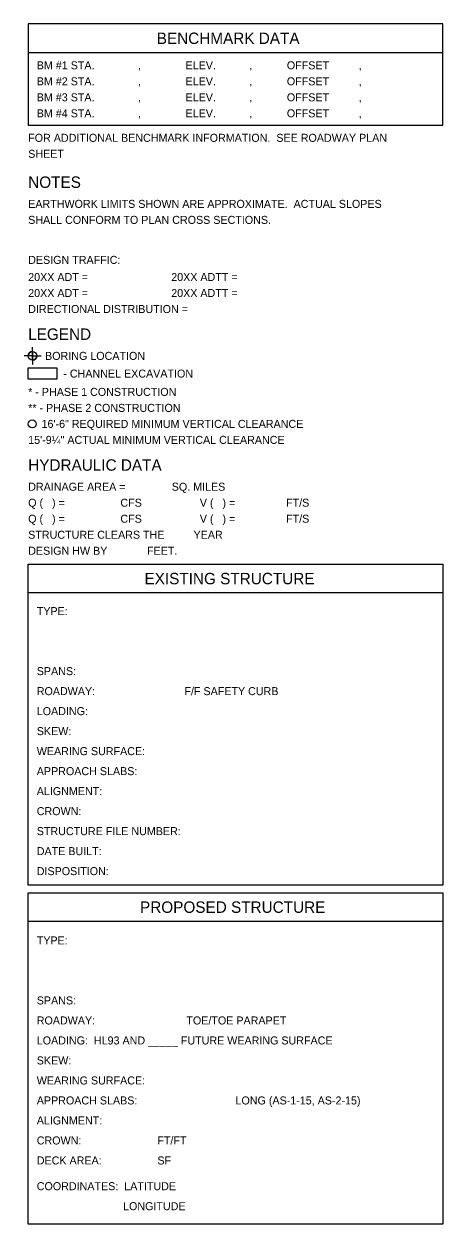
# Model space of a CAD drawing. Extents: x 0 to 112, y 0 to 22.
# Drawn here: x 60.68 to 68, y 0.5 to 21.5 of the extents above; entities that cross this region are included whole.
import ezdxf

# ---------------------------------------------------------------- set-up
doc = ezdxf.new("R2010")
doc.units = 0
doc.layers.add('GT_Project_Soil_Boring', color=7, linetype='Continuous')
doc.layers.add('SH_Data', color=7, linetype='Continuous')

msp = doc.modelspace()

# ---------------------------------------------------------------- linework, layer by layer
at = {"layer": 'GT_Project_Soil_Boring'}
for p, q in [((60.827, 15.693), (60.827, 15.843)), ((60.827, 15.768), (60.827, 15.693)), ((60.827, 15.693), (60.677, 15.693)), ((60.827, 15.693), (60.752, 15.693)), ((60.827, 15.693), (60.827, 15.543)), ((60.827, 15.693), (60.977, 15.693)), ((60.827, 15.618), (60.827, 15.693)), ((60.827, 15.693), (60.902, 15.693))]:
    msp.add_line(p, q, dxfattribs=at)
msp.add_circle((60.827, 15.693), 0.075, dxfattribs=at)
for start, end in [(90, 180), (270, 360)]:
    msp.add_arc((60.827, 15.693), 0.075, start, end, dxfattribs=at)
at = {"layer": 'SH_Data'}
for p, q in [((60.75, 21), (68, 21)), ((68, 11.545), (60.75, 11.545)), ((68, 5.795), (60.75, 5.795))]:
    msp.add_line(p, q, dxfattribs=at)
for points in [[(68, 21.5), (60.75, 21.5), (60.75, 19.727), (68, 19.727)], [(60.75, 15.482), (61.25, 15.482), (61.25, 15.282), (60.75, 15.282)], [(60.75, 12.045), (68, 12.045), (68, 6.431), (60.75, 6.431)], [(60.75, 6.295), (68, 6.295), (68, 0.5), (60.75, 0.5)]]:
    msp.add_lwpolyline(points, close=True, dxfattribs=at)
msp.add_circle((60.82, 14.501), 0.07, dxfattribs=at)

# ---------------------------------------------------------------- texts
for s, height, p in [('BENCHMARK DATA', 0.2, (62.997, 21.15)), ('BM #1 STA.', 0.14, (60.9, 20.707)), ('ELEV.', 0.14, (63.5, 20.707)), ('OFFSET', 0.14, (65.271, 20.707)), ('         ,', 0.14, (62.2, 20.707)), ('       ,', 0.14, (64.25, 20.707)), ('      ,', 0.14, (66.215, 20.707)), ('BM #2 STA.', 0.14, (60.9, 20.427)), ('         ,', 0.14, (62.2, 20.427)), ('ELEV.', 0.14, (63.5, 20.427)), ('       ,', 0.14, (64.25, 20.427)), ('OFFSET', 0.14, (65.271, 20.427)), ('      ,', 0.14, (66.215, 20.427)), ('BM #3 STA.', 0.14, (60.9, 20.147)), ('         ,', 0.14, (62.2, 20.147)), ('ELEV.', 0.14, (63.5, 20.147)), ('       ,', 0.14, (64.25, 20.147)), ('OFFSET', 0.14, (65.271, 20.147)), ('      ,', 0.14, (66.215, 20.147)), ('BM #4 STA.', 0.14, (60.9, 19.867)), ('ELEV.', 0.14, (63.5, 19.867)), ('OFFSET', 0.14, (65.271, 19.867)), ('         ,', 0.14, (62.2, 19.867)), ('       ,', 0.14, (64.25, 19.867)), ('      ,', 0.14, (66.215, 19.867)), ('FOR ADDITIONAL BENCHMARK INFORMATION.  SEE ROADWAY PLAN', 0.14, (60.75, 19.438)), ('SHEET      ', 0.14, (60.75, 19.158)), ('NOTES', 0.2, (60.75, 18.632)), ('EARTHWORK LIMITS SHOWN ARE APPROXIMATE.  ACTUAL SLOPES', 0.14, (60.75, 18.282)), ('SHALL CONFORM TO PLAN CROSS SECTIONS.', 0.14, (60.75, 18.002)), ('DESIGN TRAFFIC:', 0.14, (60.75, 17.302)), ('20XX ADT =', 0.14, (60.75, 17.002)), ('20XX ADTT =', 0.14, (63.25, 17.002)), ('20XX ADT =', 0.14, (60.75, 16.722)), ('20XX ADTT =', 0.14, (63.25, 16.722)), ('DIRECTIONAL DISTRIBUTION =', 0.14, (60.75, 16.442)), ('LEGEND', 0.2, (60.75, 15.972)), ('BORING LOCATION', 0.14, (61.045, 15.622)), ('- CHANNEL EXCAVATION', 0.14, (61.364, 15.312)), ('* - PHASE 1 CONSTRUCTION', 0.14, (60.75, 14.992)), ('** - PHASE 2 CONSTRUCTION', 0.14, (60.75, 14.712)), ('HYDRAULIC DATA', 0.2, (60.75, 13.682)), ('DRAINAGE AREA =', 0.14, (60.75, 13.332)), ('SQ. MILES', 0.14, (63.259, 13.332)), ('Q (   ) =', 0.14, (60.75, 13.052)), ('      CFS', 0.14, (62.05, 13.052)), ('V (   ) =', 0.14, (63.75, 13.052)), ('    FT/S', 0.14, (65.05, 13.052)), ('Q (   ) =', 0.14, (60.75, 12.772)), ('      CFS', 0.14, (62.05, 12.772)), ('V (   ) =', 0.14, (63.75, 12.772)), ('    FT/S', 0.14, (65.05, 12.772)), ('STRUCTURE CLEARS THE', 0.14, (60.75, 12.492)), ('YEAR', 0.14, (63.64, 12.492)), ('DESIGN HW BY', 0.14, (60.75, 12.212)), ('FEET.', 0.14, (62.827, 12.212)), ('EXISTING STRUCTURE', 0.2, (62.783, 11.695)), ('TYPE:', 0.14, (60.9, 11.155)), ('SPANS:', 0.14, (60.9, 10.105)), ('ROADWAY:', 0.14, (60.9, 9.755)), ('F/F SAFETY CURB', 0.14, (63.481, 9.755)), ('LOADING:', 0.14, (60.9, 9.405)), ('SKEW:', 0.14, (60.9, 9.055)), ('WEARING SURFACE:', 0.14, (60.9, 8.705)), ('APPROACH SLABS:', 0.14, (60.9, 8.355)), ('ALIGNMENT:', 0.14, (60.9, 8.005)), ('CROWN:', 0.14, (60.9, 7.655)), ('STRUCTURE FILE NUMBER:', 0.14, (60.9, 7.305)), ('DATE BUILT:', 0.14, (60.9, 6.955)), ('DISPOSITION:', 0.14, (60.9, 6.605)), ('PROPOSED STRUCTURE', 0.2, (62.705, 5.945)), ('TYPE:', 0.14, (60.9, 5.392)), ('SPANS:', 0.14, (60.9, 4.342)), ('ROADWAY:', 0.14, (60.9, 3.992)), ('TOE/TOE PARAPET', 0.14, (63.515, 3.992)), ('LOADING:  HL93 AND _____ FUTURE WEARING SURFACE', 0.14, (60.9, 3.642)), ('SKEW:', 0.14, (60.9, 3.292)), ('WEARING SURFACE:', 0.14, (60.9, 2.942)), ('APPROACH SLABS:', 0.14, (60.9, 2.592)), ('LONG (AS-1-15, AS-2-15)', 0.14, (64.374, 2.592)), ('ALIGNMENT:', 0.14, (60.9, 2.242)), ('CROWN:', 0.14, (60.9, 1.892)), ('FT/FT', 0.14, (63.008, 1.892)), ('DECK AREA:', 0.14, (60.9, 1.542)), ('SF', 0.14, (63.008, 1.542)), ('COORDINATES:  LATITUDE', 0.14, (60.9, 1.092)), ('                             LONGITUDE', 0.14, (60.9, 0.742))]:
    msp.add_text(s, height=height, dxfattribs=at).set_placement(p)
for s, p in [('16\'-6" REQUIRED MINIMUM VERTICAL CLEARANCE', (60.984, 14.432)), ('15\'-9¼" ACTUAL MINIMUM VERTICAL CLEARANCE', (60.75, 14.152))]:
    msp.add_text(s, height=0.14, rotation=0, dxfattribs=at).set_placement(p)

doc.saveas('drawing.dxf')
